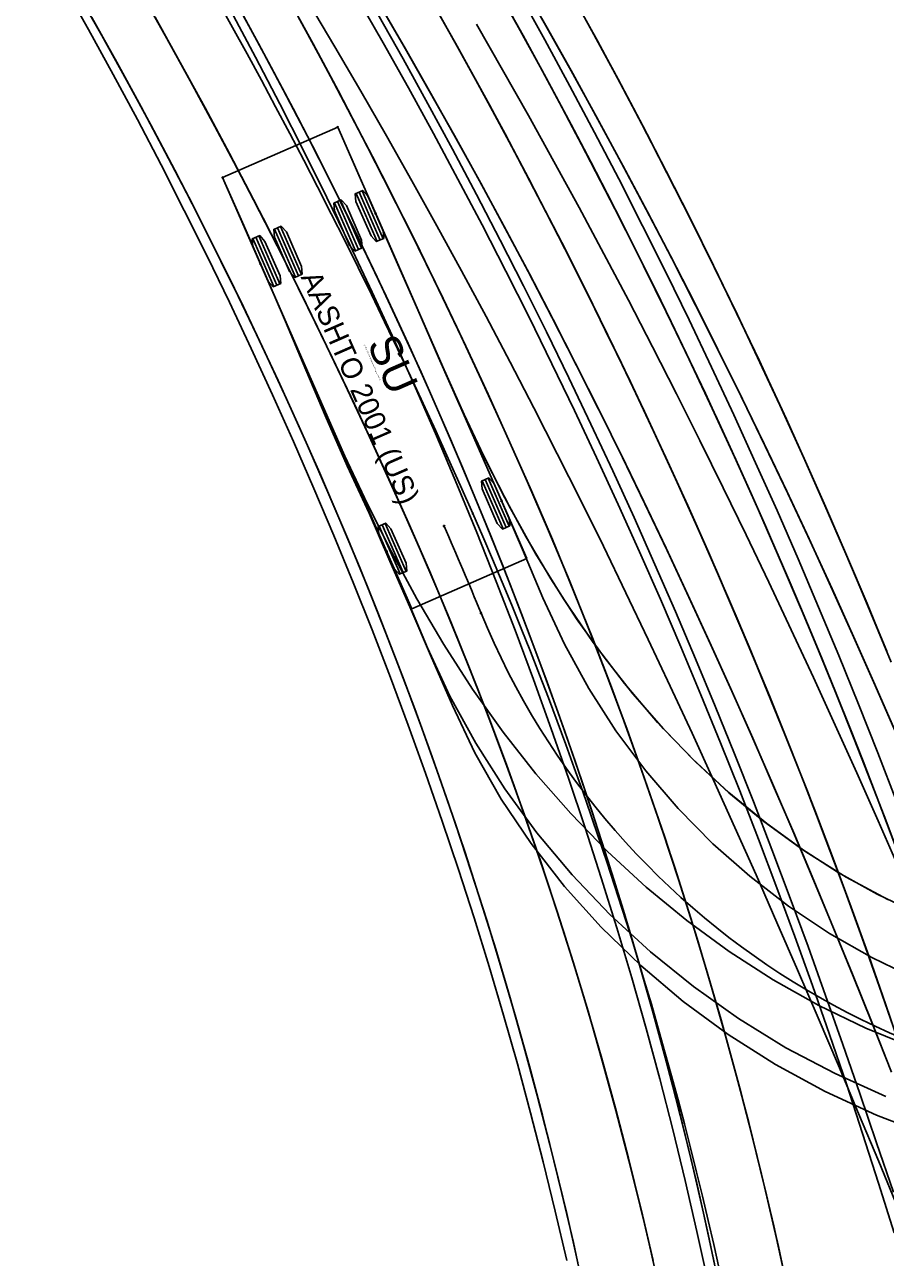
# Model space of a CAD drawing. Extents: x 916040 to 917457, y 328936 to 330267.
# Drawn here: x 916599.7 to 916654.5, y 329816 to 329894.6 of the extents above; entities that cross this region are included whole.
import ezdxf

# ---------------------------------------------------------------- set-up
doc = ezdxf.new("R2010")
doc.units = 0
for name, color, linetype in [('EB_LeftontoManchester_WB67', 7, 'Continuous'), ('EB_LeftontoManchester_WB67_v2', 7, 'Continuous'), ('NB_ThruontoManchester_WB67', 7, 'Continuous'), ('SB_LeftontoRoute25_WB67', 7, 'Continuous'), ('SB_RightontoRoute25_WB67_v2', 7, 'Continuous'), ('SB_ThruontonSacoRd_WB67', 7, 'Continuous'), ('SU_IntoDriveway_Lt', 7, 'Continuous'), ('WB_RightontoManchester_WB67', 7, 'Continuous')]:
    doc.layers.add(name, color=color, linetype=linetype)

msp = doc.modelspace()

# ---------------------------------------------------------------- linework, layer by layer
at = {"layer": 'EB_LeftontoManchester_WB67'}
for points in [[(916655.129, 329849.582), (916653.791, 329852.648), (916652.433, 329855.705), (916651.056, 329858.754), (916649.658, 329861.794), (916648.24, 329864.824), (916646.801, 329867.844), (916645.341, 329870.854), (916643.859, 329873.853), (916642.356, 329876.842), (916640.831, 329879.819), (916639.285, 329882.786), (916637.716, 329885.74), (916636.124, 329888.683), (916634.511, 329891.613), (916632.875, 329894.531), (916631.216, 329897.436)], [(916654.603, 329854.626), (916653.318, 329857.737), (916652.007, 329860.837), (916650.668, 329863.927), (916649.303, 329867.005), (916647.911, 329870.072), (916646.493, 329873.127), (916645.048, 329876.169), (916643.578, 329879.2), (916642.081, 329882.218), (916640.558, 329885.223), (916639.01, 329888.215), (916637.436, 329891.194), (916635.836, 329894.159), (916634.211, 329897.11)], [(916655.212, 329830.159), (916654.132, 329833.291), (916653.026, 329836.412), (916651.894, 329839.522), (916650.735, 329842.62), (916649.55, 329845.708), (916648.339, 329848.784), (916647.102, 329851.849), (916645.839, 329854.903), (916644.549, 329857.945), (916643.234, 329860.975), (916641.893, 329863.994), (916640.526, 329867), (916639.133, 329869.995), (916637.715, 329872.977), (916636.271, 329875.947), (916634.802, 329878.904), (916633.307, 329881.848), (916631.787, 329884.779), (916630.242, 329887.697), (916628.673, 329890.601), (916627.078, 329893.491), (916625.458, 329896.368)], [(916654.871, 329827.916), (916653.654, 329830.986), (916652.421, 329834.047), (916651.173, 329837.101), (916649.908, 329840.145), (916648.626, 329843.181), (916647.327, 329846.208), (916646.01, 329849.226), (916644.674, 329852.233), (916643.32, 329855.231), (916641.946, 329858.219), (916640.552, 329861.197), (916639.139, 329864.164), (916637.705, 329867.12), (916636.25, 329870.065), (916634.775, 329872.998), (916633.279, 329875.92), (916631.761, 329878.83), (916630.222, 329881.728), (916628.662, 329884.614), (916627.079, 329887.487), (916625.475, 329890.347), (916623.85, 329893.195), (916622.202, 329896.029)]]:
    msp.add_lwpolyline(points, dxfattribs=at)
msp.add_arc((916291.649, 329706.552), 388, 12.26429, 55.55708, dxfattribs=at)
at = {"layer": 'EB_LeftontoManchester_WB67_v2'}
for points in [[(916655.187, 329849.449), (916653.851, 329852.512), (916652.496, 329855.566), (916651.121, 329858.612), (916649.725, 329861.648), (916648.31, 329864.675), (916646.874, 329867.692), (916645.416, 329870.699), (916643.938, 329873.696), (916642.437, 329876.682), (916640.916, 329879.657), (916639.372, 329882.62), (916637.806, 329885.572), (916636.218, 329888.512), (916634.607, 329891.44), (916632.974, 329894.355), (916631.319, 329897.257)], [(916654.633, 329854.554), (916653.35, 329857.662), (916652.04, 329860.759), (916650.704, 329863.845), (916649.341, 329866.92), (916647.951, 329869.984), (916646.535, 329873.036), (916645.093, 329876.076), (916643.625, 329879.103), (916642.131, 329882.118), (916640.611, 329885.12), (916639.065, 329888.109), (916637.494, 329891.085), (916635.897, 329894.047), (916634.274, 329896.996)], [(916655.228, 329830.112), (916654.15, 329833.241), (916653.046, 329836.358), (916651.915, 329839.465), (916650.758, 329842.56), (916649.575, 329845.644), (916648.366, 329848.717), (916647.131, 329851.779), (916645.869, 329854.829), (916644.582, 329857.868), (916643.269, 329860.895), (916641.93, 329863.911), (916640.565, 329866.914), (916639.175, 329869.906), (916637.759, 329872.885), (916636.317, 329875.852), (916634.851, 329878.806), (916633.359, 329881.747), (916631.842, 329884.675), (916630.299, 329887.59), (916628.732, 329890.491), (916627.14, 329893.379), (916625.524, 329896.253)], [(916654.916, 329827.804), (916653.7, 329830.87), (916652.469, 329833.929), (916651.223, 329836.979), (916649.961, 329840.02), (916648.681, 329843.053), (916647.384, 329846.077), (916646.069, 329849.091), (916644.736, 329852.096), (916643.384, 329855.091), (916642.012, 329858.076), (916640.621, 329861.051), (916639.21, 329864.015), (916637.779, 329866.968), (916636.327, 329869.91), (916634.855, 329872.841), (916633.361, 329875.76), (916631.847, 329878.668), (916630.311, 329881.563), (916628.753, 329884.446), (916627.174, 329887.317), (916625.573, 329890.175), (916623.95, 329893.02), (916622.306, 329895.852)]]:
    msp.add_lwpolyline(points, dxfattribs=at)
msp.add_arc((916291.649, 329706.552), 388, 12.26429, 55.55708, dxfattribs=at)
at = {"layer": 'NB_ThruontoManchester_WB67'}
for points in [[(916631.225, 329896.513), (916632.843, 329893.585), (916634.435, 329890.644), (916636.003, 329887.689), (916637.545, 329884.721), (916639.061, 329881.74), (916640.552, 329878.746), (916642.018, 329875.74), (916643.457, 329872.721), (916644.871, 329869.689), (916646.259, 329866.646), (916647.621, 329863.591), (916648.956, 329860.525), (916650.265, 329857.447), (916651.548, 329854.358), (916652.804, 329851.258), (916654.034, 329848.148), (916655.241, 329845.015)], [(916634.559, 329896.482), (916636.179, 329893.527), (916637.774, 329890.559), (916639.343, 329887.576), (916640.886, 329884.58), (916642.404, 329881.572), (916643.896, 329878.55), (916645.361, 329875.515), (916646.801, 329872.468), (916648.214, 329869.409), (916649.601, 329866.337), (916650.961, 329863.254), (916652.295, 329860.159), (916653.602, 329857.053), (916654.883, 329853.936)], [(916622.198, 329895.218), (916623.805, 329892.368), (916625.387, 329889.504), (916626.945, 329886.626), (916628.478, 329883.735), (916629.987, 329880.832), (916631.471, 329877.915), (916632.929, 329874.986), (916634.363, 329872.045), (916635.771, 329869.091), (916637.154, 329866.126), (916638.512, 329863.149), (916639.844, 329860.161), (916641.15, 329857.161), (916642.431, 329854.15), (916643.686, 329851.128), (916644.914, 329848.096), (916646.117, 329845.053), (916647.299, 329841.988), (916648.456, 329838.907), (916649.592, 329835.811), (916650.708, 329832.703), (916651.806, 329829.581), (916652.89, 329826.45), (916653.964, 329823.309), (916655.032, 329820.161)], [(916626.108, 329895.222), (916627.717, 329892.339), (916629.302, 329889.443), (916630.862, 329886.534), (916632.397, 329883.611), (916633.906, 329880.675), (916635.391, 329877.726), (916636.849, 329874.765), (916638.283, 329871.791), (916639.691, 329868.805), (916641.073, 329865.807), (916642.429, 329862.797), (916643.759, 329859.776), (916645.063, 329856.743), (916646.341, 329853.699), (916647.593, 329850.644), (916648.819, 329847.579), (916650.018, 329844.503), (916651.191, 329841.417), (916652.337, 329838.321), (916653.456, 329835.216), (916654.549, 329832.101)]]:
    msp.add_lwpolyline(points, dxfattribs=at)
msp.add_arc((916291.649, 329706.552), 388, 11.6689, 55.55708, dxfattribs=at)
at = {"layer": 'SB_LeftontoRoute25_WB67'}
for points in [[(916603.015, 329896.708), (916604.62, 329893.873), (916606.197, 329891.025), (916607.744, 329888.162), (916609.262, 329885.287), (916610.751, 329882.397), (916612.208, 329879.494), (916613.634, 329876.577), (916615.029, 329873.647), (916616.392, 329870.704), (916617.722, 329867.747), (916619.019, 329864.777), (916620.282, 329861.794), (916621.512, 329858.799), (916622.707, 329855.791), (916623.867, 329852.77), (916624.992, 329849.738), (916626.081, 329846.693), (916627.134, 329843.637), (916628.151, 329840.57), (916629.131, 329837.492), (916630.075, 329834.403), (916630.981, 329831.304), (916631.849, 329828.194), (916632.682, 329825.067), (916633.476, 329821.933), (916634.227, 329818.8), (916634.934, 329815.67)], [(916607.032, 329896.744), (916608.654, 329893.869), (916610.251, 329890.98), (916611.822, 329888.076), (916613.367, 329885.159), (916614.886, 329882.228), (916616.379, 329879.284), (916617.846, 329876.327), (916619.287, 329873.357), (916620.702, 329870.374), (916622.089, 329867.379), (916623.451, 329864.371), (916624.785, 329861.352), (916626.083, 329858.324), (916627.341, 329855.28), (916628.558, 329852.222), (916629.736, 329849.15), (916630.873, 329846.063), (916631.97, 329842.963), (916633.027, 329839.85), (916634.043, 329836.724), (916635.018, 329833.585), (916635.953, 329830.435), (916636.847, 329827.273), (916637.7, 329824.1), (916638.511, 329820.917), (916639.282, 329817.724), (916640.011, 329814.521)], [(916613.651, 329895.108), (916615.239, 329892.172), (916616.797, 329889.221), (916618.325, 329886.254), (916619.822, 329883.272), (916621.288, 329880.275), (916622.722, 329877.264), (916624.123, 329874.237), (916625.491, 329871.196), (916626.825, 329868.14), (916628.126, 329865.07), (916629.391, 329861.986), (916630.622, 329858.888), (916631.817, 329855.777), (916632.976, 329852.653), (916634.099, 329849.515), (916635.185, 329846.365), (916636.233, 329843.202), (916637.244, 329840.028), (916638.217, 329836.842), (916639.152, 329833.644), (916640.048, 329830.436), (916640.908, 329827.209), (916641.727, 329823.973), (916642.504, 329820.734), (916643.236, 329817.493), (916643.923, 329814.251)], [(916617.106, 329895.1), (916618.713, 329892.135), (916620.294, 329889.157), (916621.849, 329886.164), (916623.376, 329883.158), (916624.878, 329880.139), (916626.352, 329877.106), (916627.799, 329874.061), (916629.219, 329871.002), (916630.613, 329867.932), (916631.978, 329864.849), (916633.311, 329861.747), (916634.604, 329858.627), (916635.858, 329855.49), (916637.071, 329852.335), (916638.245, 329849.164), (916639.377, 329845.978), (916640.469, 329842.776), (916641.52, 329839.56), (916642.529, 329836.331), (916643.497, 329833.088), (916644.423, 329829.832), (916645.307, 329826.565), (916646.149, 329823.286), (916646.948, 329819.996), (916647.705, 329816.696), (916648.42, 329813.387)]]:
    msp.add_lwpolyline(points, dxfattribs=at)
msp.add_circle((916628.248, 329863.406), 0.0417, dxfattribs=at)
msp.add_circle((916628.248, 329863.406), 0.0417, dxfattribs=at)
for centre, radius, start, end in [((916283.416, 329712.267), 376.5, 23.66768, 42.35327), ((916391.491, 329759.636), 258.5, 1.1947, 23.66768)]:
    msp.add_arc(centre, radius, start, end, dxfattribs=at)
at = {"layer": 'SB_RightontoRoute25_WB67_v2'}
for points in [[(916613.008, 329896.278), (916614.608, 329893.348), (916616.178, 329890.403), (916617.718, 329887.442), (916619.227, 329884.467), (916620.705, 329881.476), (916622.152, 329878.47), (916623.566, 329875.45), (916624.948, 329872.414), (916626.296, 329869.364), (916627.61, 329866.3), (916628.889, 329863.222), (916630.134, 329860.129), (916631.343, 329857.023), (916632.517, 329853.904), (916633.654, 329850.772), (916634.755, 329847.626), (916635.818, 329844.469), (916636.844, 329841.299), (916637.833, 329838.118), (916638.783, 329834.925), (916639.694, 329831.721), (916640.567, 329828.506), (916641.4, 329825.283), (916642.192, 329822.058), (916642.94, 329818.83), (916643.643, 329815.6)], [(916616.456, 329896.282), (916618.074, 329893.323), (916619.665, 329890.35), (916621.23, 329887.363), (916622.768, 329884.362), (916624.28, 329881.348), (916625.765, 329878.321), (916627.223, 329875.281), (916628.655, 329872.227), (916630.059, 329869.162), (916631.435, 329866.083), (916632.783, 329862.99), (916634.092, 329859.878), (916635.361, 329856.747), (916636.591, 329853.599), (916637.78, 329850.435), (916638.929, 329847.254), (916640.037, 329844.059), (916641.104, 329840.848), (916642.13, 329837.624), (916643.115, 329834.386), (916644.057, 329831.136), (916644.958, 329827.873), (916645.817, 329824.599), (916646.634, 329821.313), (916647.408, 329818.017), (916648.139, 329814.712)], [(916603.981, 329895.009), (916605.569, 329892.166), (916607.129, 329889.309), (916608.659, 329886.439), (916610.159, 329883.554), (916611.629, 329880.657), (916613.068, 329877.745), (916614.475, 329874.821), (916615.851, 329871.883), (916617.194, 329868.931), (916618.504, 329865.967), (916619.781, 329862.989), (916621.024, 329859.999), (916622.233, 329856.996), (916623.407, 329853.98), (916624.546, 329850.952), (916625.649, 329847.913), (916626.717, 329844.861), (916627.749, 329841.798), (916628.744, 329838.724), (916629.702, 329835.64), (916630.623, 329832.544), (916631.506, 329829.439), (916632.352, 329826.323), (916633.159, 329823.202), (916633.925, 329820.08), (916634.648, 329816.96), (916635.326, 329813.844)], [(916608.009, 329895.021), (916609.615, 329892.137), (916611.197, 329889.239), (916612.752, 329886.328), (916614.282, 329883.402), (916615.785, 329880.463), (916617.263, 329877.511), (916618.714, 329874.546), (916620.139, 329871.569), (916621.537, 329868.578), (916622.909, 329865.576), (916624.255, 329862.561), (916625.569, 329859.537), (916626.842, 329856.5), (916628.076, 329853.447), (916629.27, 329850.381), (916630.423, 329847.3), (916631.536, 329844.205), (916632.609, 329841.097), (916633.641, 329837.976), (916634.633, 329834.842), (916635.584, 329831.697), (916636.494, 329828.539), (916637.364, 329825.371), (916638.192, 329822.192), (916638.979, 329819.002), (916639.724, 329815.803)]]:
    msp.add_lwpolyline(points, dxfattribs=at)
msp.add_circle((916628.248, 329863.406), 0.0417, dxfattribs=at)
msp.add_circle((916628.248, 329863.406), 0.0417, dxfattribs=at)
for centre, radius, start, end in [((916283.416, 329712.267), 376.5, 23.66768, 42.35327), ((916391.491, 329759.636), 258.5, 1.1947, 23.66768)]:
    msp.add_arc(centre, radius, start, end, dxfattribs=at)
at = {"layer": 'SB_ThruontonSacoRd_WB67'}
for points in [[(916634.225, 329815.813), (916633.5, 329818.954), (916632.735, 329822.089), (916631.929, 329825.216), (916631.085, 329828.335), (916630.202, 329831.446), (916629.281, 329834.548), (916628.323, 329837.641), (916627.328, 329840.724), (916626.298, 329843.798), (916625.232, 329846.861), (916624.131, 329849.914), (916622.996, 329852.956), (916621.827, 329855.987), (916620.625, 329859.007), (916619.39, 329862.015), (916618.123, 329865.01), (916616.825, 329867.994), (916615.495, 329870.965), (916614.134, 329873.922), (916612.744, 329876.867), (916611.323, 329879.799), (916609.872, 329882.717), (916608.393, 329885.621), (916606.884, 329888.511), (916605.347, 329891.387), (916603.782, 329894.248), (916602.189, 329897.094)], [(916643.228, 329814.41), (916642.521, 329817.666), (916641.771, 329820.913), (916640.98, 329824.152), (916640.149, 329827.381), (916639.277, 329830.601), (916638.366, 329833.811), (916637.417, 329837.01), (916636.429, 329840.198), (916635.404, 329843.376), (916634.343, 329846.542), (916633.245, 329849.696), (916632.112, 329852.838), (916630.944, 329855.967), (916629.742, 329859.084), (916628.507, 329862.189), (916627.238, 329865.28), (916625.936, 329868.358), (916624.603, 329871.422), (916623.237, 329874.473), (916621.84, 329877.51), (916620.413, 329880.532), (916618.955, 329883.541), (916617.467, 329886.534), (916615.949, 329889.513), (916614.402, 329892.477), (916612.826, 329895.426)], [(916648.31, 329813.896), (916647.588, 329817.21), (916646.823, 329820.513), (916646.016, 329823.805), (916645.167, 329827.086), (916644.275, 329830.356), (916643.341, 329833.613), (916642.365, 329836.858), (916641.348, 329840.09), (916640.289, 329843.308), (916639.188, 329846.512), (916638.046, 329849.701), (916636.864, 329852.875), (916635.64, 329856.034), (916634.376, 329859.176), (916633.071, 329862.302), (916631.727, 329865.41), (916630.352, 329868.502), (916628.951, 329871.579), (916627.522, 329874.643), (916626.067, 329877.692), (916624.586, 329880.728), (916623.077, 329883.749), (916621.543, 329886.756), (916619.982, 329889.749), (916618.394, 329892.727), (916616.781, 329895.691)], [(916639.692, 329815.957), (916638.945, 329819.151), (916638.157, 329822.335), (916637.328, 329825.51), (916636.458, 329828.674), (916635.548, 329831.827), (916634.596, 329834.968), (916633.604, 329838.097), (916632.572, 329841.213), (916631.5, 329844.316), (916630.388, 329847.404), (916629.236, 329850.479), (916628.044, 329853.538), (916626.813, 329856.582), (916625.543, 329859.609), (916624.233, 329862.621), (916622.891, 329865.625), (916621.522, 329868.619), (916620.126, 329871.601), (916618.704, 329874.573), (916617.254, 329877.532), (916615.779, 329880.48), (916614.277, 329883.415), (916612.748, 329886.337), (916611.194, 329889.246), (916609.614, 329892.142), (916608.008, 329895.023)]]:
    msp.add_lwpolyline(points, dxfattribs=at)
msp.add_circle((916628.248, 329863.406), 0.0417, dxfattribs=at)
msp.add_circle((916628.248, 329863.406), 0.0417, dxfattribs=at)
for centre, radius, start, end in [((916283.416, 329712.267), 376.5, 23.66768, 42.35327), ((916391.491, 329759.636), 258.5, 1.1947, 23.66768)]:
    msp.add_arc(centre, radius, start, end, dxfattribs=at)
at = {"layer": 'SU_IntoDriveway_Lt'}
for p, q in [((916619.643, 329888.022), (916612.316, 329884.81)), ((916631.686, 329860.545), (916619.643, 329888.022)), ((916612.316, 329884.81), (916624.359, 329857.334)), ((916622.148, 329880.749), (916620.81, 329883.802)), ((916622.339, 329880.833), (916621.001, 329883.886)), ((916622.53, 329880.916), (916621.192, 329883.969)), ((916620.774, 329880.147), (916619.436, 329883.2)), ((916620.965, 329880.23), (916619.627, 329883.283)), ((916621.156, 329880.314), (916619.818, 329883.367)), ((916616.958, 329878.474), (916615.62, 329881.527)), ((916617.149, 329878.558), (916615.811, 329881.611)), ((916617.34, 329878.641), (916616.001, 329881.694)), ((916615.584, 329877.872), (916614.246, 329880.925)), ((916615.775, 329877.956), (916614.437, 329881.009)), ((916615.966, 329878.039), (916614.628, 329881.092)), ((916630.367, 329862.515), (916629.029, 329865.568)), ((916630.558, 329862.598), (916629.22, 329865.651)), ((916630.177, 329862.431), (916628.839, 329865.484)), ((916623.613, 329859.554), (916622.275, 329862.607)), ((916623.804, 329859.638), (916622.465, 329862.691)), ((916623.994, 329859.721), (916622.656, 329862.774)), ((916624.359, 329857.334), (916631.686, 329860.545)), ((916631.686, 329860.545), (916631.686, 329860.545))]:
    msp.add_line(p, q, dxfattribs=at)
for points in [[(916619.643, 329888.022), (916620.984, 329884.97), (916622.33, 329881.92), (916623.658, 329878.863), (916624.995, 329875.81), (916626.333, 329872.757), (916627.69, 329869.712), (916629.122, 329866.702), (916630.64, 329863.735), (916632.263, 329860.824), (916632.263, 329860.824), (916634.016, 329857.967), (916635.905, 329855.197), (916637.906, 329852.565), (916640.018, 329850.086), (916642.236, 329847.768), (916644.553, 329845.62), (916646.963, 329843.646), (916649.459, 329841.851), (916652.031, 329840.237), (916654.673, 329838.808)], [(916612.316, 329884.81), (916613.654, 329881.757), (916614.992, 329878.704), (916616.316, 329875.645), (916617.606, 329872.571), (916618.906, 329869.499), (916620.244, 329866.444), (916621.638, 329863.42), (916622.965, 329860.362), (916624.292, 329857.304), (916624.292, 329857.304), (916624.292, 329857.304), (916625.623, 329854.236), (916626.95, 329851.178), (916628.378, 329848.156), (916630.052, 329845.214), (916631.959, 329842.372), (916634.085, 329839.645), (916636.418, 329837.051), (916638.943, 329834.606), (916641.646, 329832.323), (916644.513, 329830.217), (916647.529, 329828.298), (916650.681, 329826.58), (916653.951, 329825.07), (916657.325, 329823.778)], [(916622.051, 329882.526), (916623.396, 329879.455), (916624.735, 329876.379), (916626.056, 329873.347), (916627.387, 329870.372), (916628.75, 329867.466), (916630.165, 329864.638), (916631.648, 329861.896), (916633.21, 329859.246), (916634.859, 329856.694), (916636.602, 329854.246), (916638.442, 329851.908), (916640.381, 329849.686), (916642.42, 329847.587), (916644.556, 329845.617), (916646.787, 329843.782), (916649.109, 329842.088), (916651.515, 329840.543), (916654.001, 329839.15), (916656.558, 329837.917)], [(916614.724, 329879.315), (916616.066, 329876.251), (916617.397, 329873.194), (916618.731, 329870.131), (916620.106, 329867.056), (916621.543, 329863.993), (916623.059, 329860.962), (916624.672, 329857.98), (916626.391, 329855.062), (916628.226, 329852.221), (916630.184, 329849.47), (916632.268, 329846.821), (916634.479, 329844.286), (916636.818, 329841.876), (916639.281, 329839.602), (916641.866, 329837.475), (916644.565, 329835.504), (916647.373, 329833.698), (916650.282, 329832.067), (916653.282, 329830.618), (916656.363, 329829.359)], [(916630.08, 329864.209), (916631.41, 329861.119), (916632.7, 329858.027), (916634.075, 329855.076), (916635.632, 329852.251), (916637.364, 329849.561), (916639.264, 329847.011), (916641.323, 329844.611), (916643.532, 329842.368), (916645.881, 329840.289), (916648.359, 329838.382), (916650.955, 329836.652), (916653.657, 329835.106), (916656.452, 329833.749)], [(916622.753, 329860.997), (916624.072, 329857.934), (916625.357, 329854.852), (916626.79, 329851.777), (916628.435, 329848.776), (916630.285, 329845.867), (916632.331, 329843.068), (916634.565, 329840.393), (916636.976, 329837.858), (916639.554, 329835.475), (916642.29, 329833.259), (916645.17, 329831.22), (916648.182, 329829.369), (916651.315, 329827.717), (916654.553, 329826.27)]]:
    msp.add_lwpolyline(points, dxfattribs=at)
for points in [[(916622.577, 329880.937), (916622.101, 329880.728), (916621.77, 329881.093), (916620.806, 329883.291), (916620.763, 329883.781), (916621.239, 329883.99), (916621.57, 329883.625), (916622.533, 329881.427)], [(916621.203, 329880.335), (916620.727, 329880.126), (916620.396, 329880.491), (916619.433, 329882.689), (916619.389, 329883.179), (916619.865, 329883.388), (916620.196, 329883.023), (916621.159, 329880.825)], [(916617.387, 329878.662), (916616.911, 329878.453), (916616.58, 329878.818), (916615.616, 329881.016), (916615.573, 329881.506), (916616.049, 329881.715), (916616.38, 329881.351), (916617.343, 329879.152)], [(916616.013, 329878.06), (916615.537, 329877.851), (916615.206, 329878.216), (916614.243, 329880.414), (916614.199, 329880.904), (916614.675, 329881.113), (916615.006, 329880.748), (916615.969, 329878.55)], [(916630.606, 329862.619), (916630.129, 329862.41), (916629.798, 329862.775), (916628.835, 329864.973), (916628.791, 329865.463), (916629.267, 329865.672), (916629.598, 329865.308), (916630.562, 329863.109)], [(916624.042, 329859.742), (916623.565, 329859.533), (916623.235, 329859.898), (916622.271, 329862.096), (916622.227, 329862.586), (916622.704, 329862.795), (916623.034, 329862.431), (916623.998, 329860.233)]]:
    msp.add_lwpolyline(points, close=True, dxfattribs=at)
for centre in [(916619.643, 329888.022), (916612.316, 329884.81), (916622.051, 329882.526), (916614.724, 329879.315), (916630.08, 329864.209), (916626.416, 329862.603), (916622.753, 329860.997), (916628.771, 329857.053), (916628.771, 329857.053)]:
    msp.add_circle(centre, 0.0417, dxfattribs=at)
for centre, radius, start, end in [((916391.491, 329759.636), 256.5, 22.32105, 23.66768), ((916675.025, 329876.043), 50, 202.32105, 276.25336)]:
    msp.add_arc(centre, radius, start, end, dxfattribs=at)
at = {"layer": 'WB_RightontoManchester_WB67'}
for points in [[(916655.182, 329842.148), (916653.993, 329845.293), (916652.776, 329848.429), (916651.532, 329851.555), (916650.261, 329854.671), (916648.962, 329857.776), (916647.636, 329860.871), (916646.284, 329863.955), (916644.904, 329867.027), (916643.497, 329870.088), (916642.064, 329873.136), (916640.605, 329876.172), (916639.119, 329879.196), (916637.606, 329882.206), (916636.068, 329885.204), (916634.504, 329888.188), (916632.913, 329891.159), (916631.297, 329894.115), (916629.655, 329897.058)], [(916655.07, 329817.571), (916654.084, 329820.747), (916653.072, 329823.911), (916652.034, 329827.063), (916650.969, 329830.203), (916649.878, 329833.332), (916648.759, 329836.449), (916647.615, 329839.554), (916646.444, 329842.649), (916645.246, 329845.731), (916644.022, 329848.802), (916642.772, 329851.862), (916641.495, 329854.91), (916640.192, 329857.946), (916638.863, 329860.971), (916637.507, 329863.983), (916636.126, 329866.983), (916634.719, 329869.97), (916633.286, 329872.945), (916631.828, 329875.908), (916630.343, 329878.857), (916628.834, 329881.793), (916627.298, 329884.716), (916625.738, 329887.625), (916624.152, 329890.521), (916622.542, 329893.402), (916620.906, 329896.269)], [(916655.364, 329819.051), (916654.094, 329822.118), (916652.817, 329825.179), (916651.531, 329828.234), (916650.237, 329831.282), (916648.931, 329834.323), (916647.614, 329837.357), (916646.284, 329840.383), (916644.941, 329843.4), (916643.584, 329846.41), (916642.211, 329849.41), (916640.823, 329852.401), (916639.419, 329855.383), (916637.998, 329858.355), (916636.559, 329861.317), (916635.102, 329864.268), (916633.627, 329867.209), (916632.133, 329870.138), (916630.62, 329873.057), (916629.087, 329875.964), (916627.534, 329878.86), (916625.962, 329881.743), (916624.369, 329884.614), (916622.755, 329887.473), (916621.12, 329890.318), (916619.465, 329893.151), (916617.788, 329895.971)], [(916655.404, 329840.757), (916654.059, 329843.818), (916652.699, 329846.874), (916651.324, 329849.923), (916649.932, 329852.964), (916648.524, 329855.999), (916647.099, 329859.025), (916645.656, 329862.043), (916644.194, 329865.052), (916642.713, 329868.052), (916641.213, 329871.042), (916639.693, 329874.023), (916638.154, 329876.993), (916636.593, 329879.952), (916635.012, 329882.9), (916633.411, 329885.837), (916631.787, 329888.762), (916630.143, 329891.676), (916628.477, 329894.577)]]:
    msp.add_lwpolyline(points, dxfattribs=at)
msp.add_arc((916291.649, 329706.552), 384, 12.55823, 55.55708, dxfattribs=at)

# ---------------------------------------------------------------- texts
at = {"layer": 'SU_IntoDriveway_Lt'}
for s, height, p in [('AASHTO 2001 (US)', 1.33333, (916617.267, 329878.48)), ('(c) 2016 Transoft Solutions, Inc. All rights reserved.', 0.08, (916621.31, 329874.155)), ('SU', 2, (916621.497, 329874.225))]:
    msp.add_text(s, height=height, rotation=293.66768, dxfattribs=at).set_placement(p)

doc.saveas('drawing.dxf')
